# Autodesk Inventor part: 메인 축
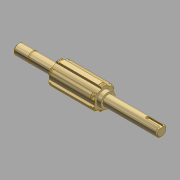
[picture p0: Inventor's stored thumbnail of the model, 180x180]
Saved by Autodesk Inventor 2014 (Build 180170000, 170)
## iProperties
Created: 2015-11
Part Number: 메인 축
Document SubType Name: 모델링
Designer: mdu
Mass: 21.4461 g
Surface Area: 72.5104 cm^2
Volume: 21.4461 cm^3
Density: 1 g/cm^3
Material: 일반
Appearance: 기본값
변환 표준: STEP AP214IS
파일 이름: C:\Users\SeoGD\Desktop\?쒗뿕\硫붿씤 異?.stp
전처리기: Build: 253, Release: 2010 SP1 - Date: Wed 07/29/2009
전송 단위: 밀리미터
불확실성: 0.01
Author: mdu
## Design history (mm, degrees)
sketch "스케치1"
  geometry: L1 (-69.5, 0)-(69.5, 0); L2 (69.5, 0)-(69.5, 5); L3 (69.5, 5)-(55.5, 5); L4 (55.5, 5)-(55.5, 4.8); L5 (55.5, 4.8)-(54.35, 4.8); L6 (54.35, 4.8)-(54.35, 5); L7 (54.35, 5)-(30.5, 5); L8 (30.5, 5)-(30.5, 9); L9 (30.5, 9)-(-13.5, 9); L10 (-13.5, 9)-(-13.5, 7); L11 (-13.5, 7)-(-17.5, 7); L12 (-17.5, 7)-(-17.5, 5); L13 (-17.5, 5)-(-69.5, 5); L14 (-69.5, 5)-(-69.5, 0); 2 further points
  constraints: 28 end point, 9 parallel, 4 collinear, 2 perpendicular, 1 coincident, 1 horizontal, 1 midpoint
  dimensions: "d2" = 1.15 distance between parallel lines of L6 L4; "d3" = 10 diameter of L3 L1; "d4" = 9.6 diameter of L5 L1; "d6" = 44 distance between parallel lines of L10 L8; "d7" = 4 distance between parallel lines of L12 L10; "d8" = 14 diameter of L11 L1; "d9" = 18 diameter of L9 L1; "d33" = 52 distance from line of L12.end L14; "d37" = 39 distance between parallel lines of L8 L2; "d38" = 14 distance between parallel lines of L2 L4
revolve "회전1" sketch "스케치1" stored, may be unused: angle "d10" = 90 deg
sketch "스케치2"
  geometry: L1 (2.5, 10.712)-(2.5, 8.646); L2 (-2.5, 10.712)-(-2.5, 8.646); A1 r 9 centre (0, 0) between (2.5, 8.646) and (-2.5, 8.646) reference; A2 r 11 centre (0, 0) between (2.5, 10.712) and (-2.5, 10.712); 1 further point
  constraints: 4 end point, 4 point on circle, 2 parallel, 1 centre point, 1 coincident, 1 vertical
  dimensions: "d11" = 22 diameter of A2; "d12" = 5 distance between parallel lines of L1 L2
extrude "돌출1" join sketch "스케치2" stored distance "d13" = 10; taper "d14" = 0 deg
chamfer "모따기1" distance "d15" = 1; stored, may be unused: second distance "d16" = 2, angle "d17" = 45 deg
node "작업 평면1"
node "작업 평면2"
sketch "스케치3"
  geometry: L1 (2.5, 10.712)-(2.5, 10.198); L2 (-2.5, 10.712)-(-2.5, 10.198); A1 r 11 centre (0, 0) between (2.5, 10.712) and (-2.5, 10.712) reference; A2 r 10.5 centre (0, 0) between (2.5, 10.198) and (-2.5, 10.198); 1 further point
  constraints: 4 end point, 2 point on circle, 1 centre point, 1 coincident, 1 parallel, 1 vertical
  dimensions: "d19" = 21 diameter of A2
extrude "돌출2" cut sketch "스케치3" distance "d20" = 1.35; taper "d21" = 0 deg
node "작업 평면3"
sketch "스케치4"
  geometry: L1 (-26, -5)-(-26, 5) reference; L2 (-26, 1.5)-(-12.5, 1.5); L3 (-12.5, -1.5)-(-26, -1.5); A1 r 1.5 centre (-12.5, 0) between (-12.5, -1.5) and (-12.5, 1.5); 2 further points
  constraints: 4 end point, 2 perpendicular, 2 point on circle, 2 point on line, 2 tangent, 1 centre point, 1 horizontal alignment, 1 midpoint
  dimensions: "d25" = 3 distance between parallel lines of L3 L2; "d26" = 15 dimension on A1 L1
extrude "돌출3" cut sketch "스케치4" distance "d27" = 1.8; taper "d28" = 0 deg
chamfer "모따기2" distance "d29" = 1; stored, may be unused: second distance "d30" = 2, angle "d31" = 45 deg
node "솔리드1"
node "솔리드 본체"
node "곡면 본체"
mirror "대칭1"
pattern_circular "원형 패턴1" dims "d23" = 360 deg
node "솔리드2"
other parameters: "d18" = -1.65
